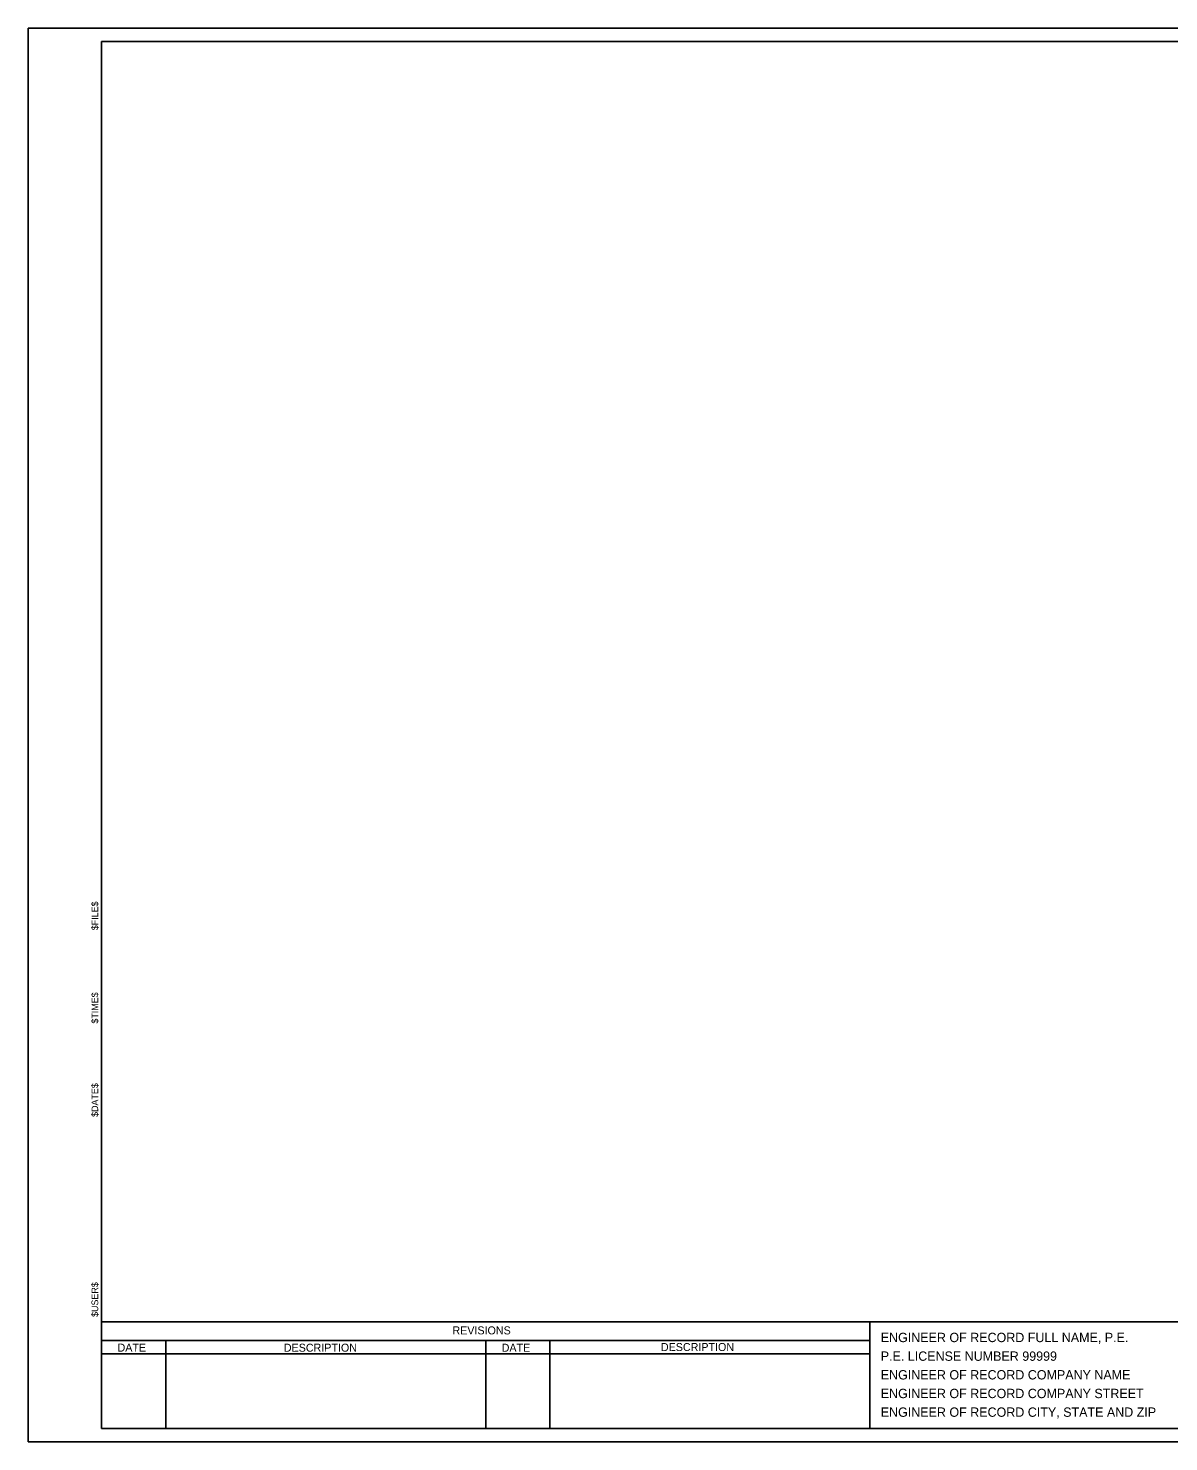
# Model space of a CAD drawing. Extents: x -830008.4 to -829991.9, y 1290284.1 to 1290294.7.
# Drawn here: x -830008.37 to -829999.82, y 1290284.08 to 1290294.68 of the extents above; entities that cross this region are included whole.
import ezdxf

# ---------------------------------------------------------------- set-up
doc = ezdxf.new("R2010")
doc.units = 0
for name, color, linetype in [('AdhocPoint_dp', 7, 'Continuous'), ('PlotBorder_dp', 7, 'Continuous'), ('SheetBorder_dp', 7, 'Continuous'), ('SheetLines_dp', 7, 'Continuous'), ('TextMisc', 7, 'Continuous'), ('TextNotes', 7, 'Continuous')]:
    doc.layers.add(name, color=color, linetype=linetype)

msp = doc.modelspace()

# ---------------------------------------------------------------- linework, layer by layer
at = {"layer": 'AdhocPoint_dp'}
msp.add_line((-830008.374, 1290284.078), (-830008.374, 1290284.078), dxfattribs=at)
at = {"layer": 'PlotBorder_dp'}
msp.add_lwpolyline([(-830008.374, 1290284.078), (-829991.874, 1290284.078), (-829991.874, 1290294.678), (-830008.374, 1290294.678)], close=True, dxfattribs=at)
at = {"layer": 'SheetBorder_dp'}
for p, q in [((-830007.824, 1290294.578), (-830007.824, 1290284.178)), ((-830007.824, 1290294.578), (-829992.424, 1290294.578)), ((-830007.824, 1290284.978), (-829992.424, 1290284.978)), ((-830007.824, 1290284.178), (-829992.424, 1290284.178))]:
    msp.add_line(p, q, dxfattribs=at)
at = {"layer": 'SheetLines_dp'}
for p, q in [((-830002.064, 1290284.978), (-830002.064, 1290284.178)), ((-830007.824, 1290284.838), (-830002.064, 1290284.838)), ((-830007.344, 1290284.838), (-830007.344, 1290284.178)), ((-830004.944, 1290284.838), (-830004.944, 1290284.178)), ((-830004.464, 1290284.838), (-830004.464, 1290284.178)), ((-830007.824, 1290284.738), (-830002.064, 1290284.738))]:
    msp.add_line(p, q, dxfattribs=at)

# ---------------------------------------------------------------- texts
at = {"layer": 'TextMisc'}
for s, height, rotation, p in [('$FILE$', 0.05, 90, (-830007.85, 1290287.914)), ('$TIME$', 0.05, 90, (-830007.85, 1290287.214)), ('$DATE$', 0.05, 90, (-830007.85, 1290286.514)), ('$USER$', 0.05, 90, (-830007.85, 1290285.014)), ('DATE', 0.06, 359.8693, (-830007.705, 1290284.754)), ('DESCRIPTION', 0.06, 0.0498, (-830006.458, 1290284.753)), ('DATE', 0.06, 359.8693, (-830004.825, 1290284.753)), ('DESCRIPTION', 0.06, 0.0498, (-830003.631, 1290284.758))]:
    msp.add_text(s, height=height, rotation=rotation, dxfattribs=at).set_placement(p)
msp.add_text('REVISIONS', height=0.06, dxfattribs=at).set_placement((-830005.194, 1290284.883))
at = {"layer": 'TextNotes'}
for s, p in [('ENGINEER OF RECORD FULL NAME, P.E.', (-830001.983, 1290284.825)), ('P.E. LICENSE NUMBER 99999', (-830001.983, 1290284.685)), ('ENGINEER OF RECORD COMPANY NAME', (-830001.983, 1290284.545)), ('ENGINEER OF RECORD COMPANY STREET', (-830001.983, 1290284.405)), ('ENGINEER OF RECORD CITY, STATE AND ZIP', (-830001.983, 1290284.265))]:
    msp.add_text(s, height=0.07, dxfattribs=at).set_placement(p)

doc.saveas('drawing.dxf')
